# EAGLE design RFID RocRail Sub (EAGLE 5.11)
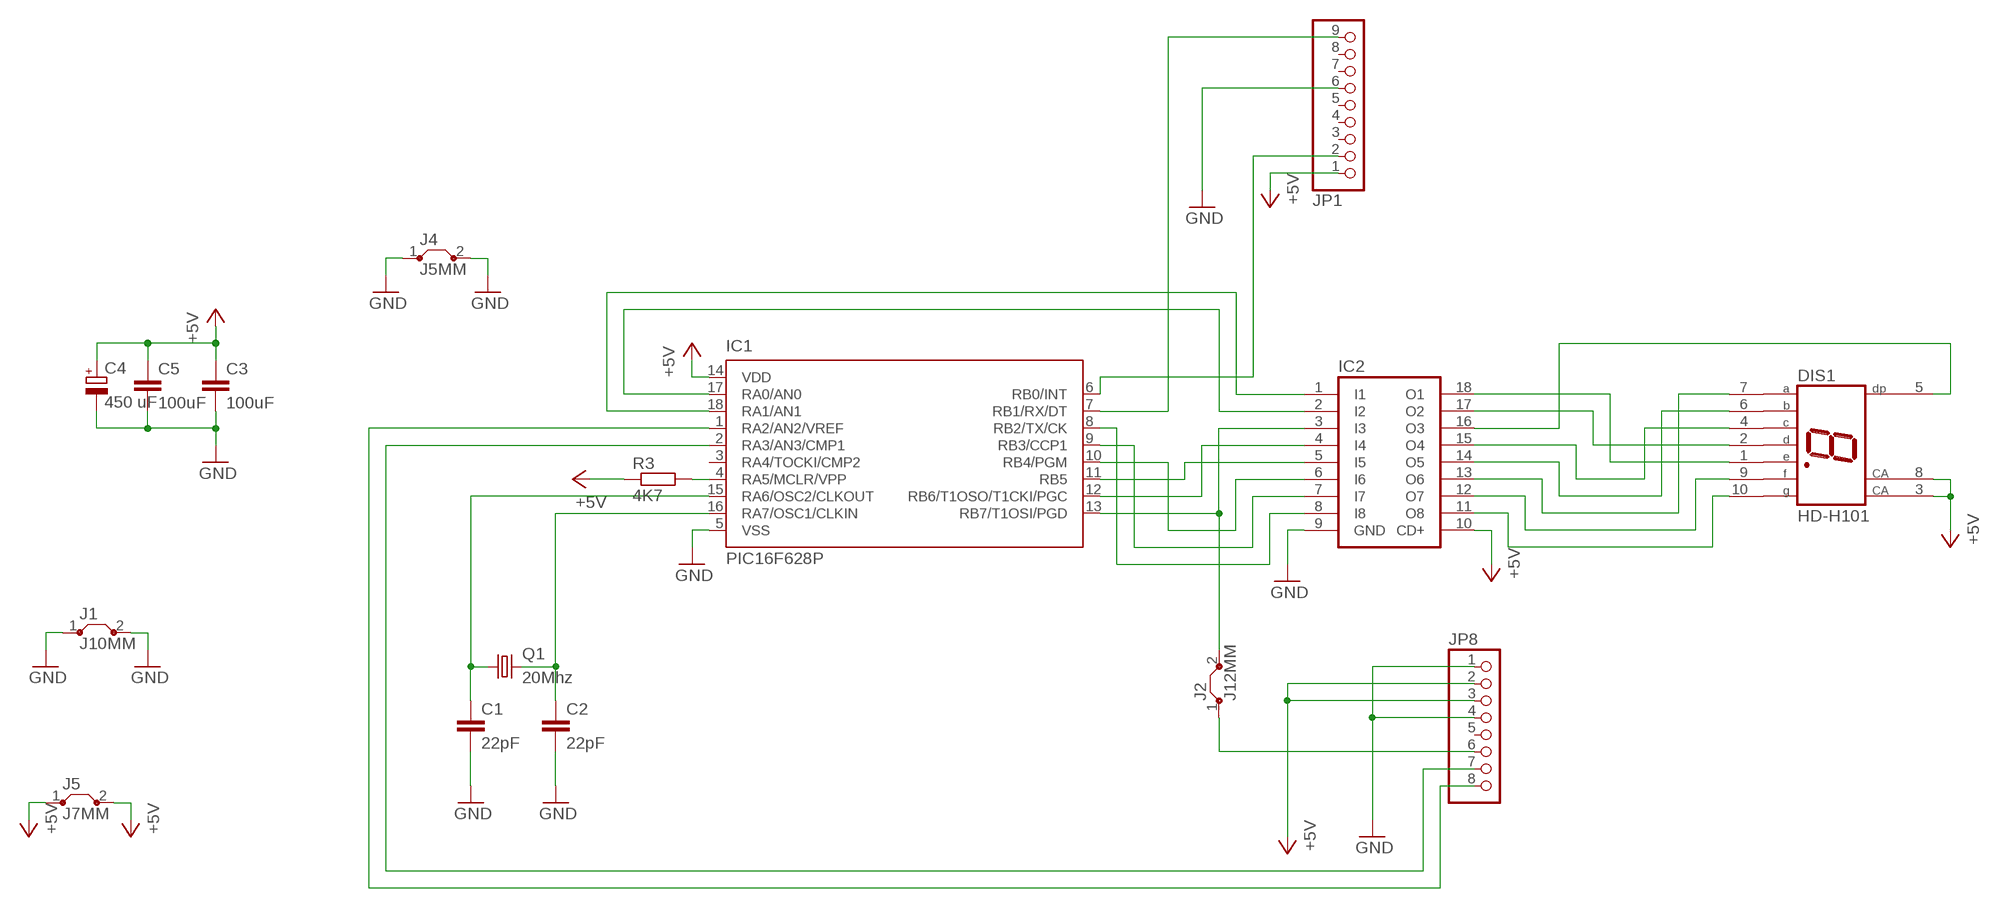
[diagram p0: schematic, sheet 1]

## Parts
C1  22pF  C-EU050-025X075  [C050-025X075]
C2  22pF  C-EU050-025X075  [C050-025X075]
C3  100uF  C-EU050-025X075  [C050-025X075]
C4  450 uF  CPOL-EUE5-13  [E5-13]
C5  100uF  C-EU050-025X075  [C050-025X075]
DIS1  HD-H101  [HDSP-M]
IC1  PIC16F628P  [DIL18]
IC2  ULN2803A  [DIL18]
J1  J10MM  [10]
J2  J12MM  [12]
J4  J5MM  [05]
J5  J7MM  [07]
JP1  PINHD-1X9  [1X09]
JP8  PINHD-1X8  [1X08]
Q1  20Mhz  CRYSTALHC18U-V  [HC18U-V]
R3  4K7  R-EU_0207/10  [0207/10]

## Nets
+5V: C3.1 C4.+ C5.1 DIS1.3(CA) DIS1.8(CA) IC1.14(VDD) IC2.10(CD+) J5.1 J5.2 JP1.1 JP8.2 JP8.3 R3.1
GND: C1.2 C2.2 C3.2 C4.- C5.2 IC1.5(VSS) IC2.9(GND) J1.1 J1.2 J4.1 J4.2 JP1.6 JP8.1 JP8.4
N$1: DIS1.1(E) IC2.18(O1)
N$2: DIS1.2(D) IC2.17(O2)
N$3: DIS1.5(DP) IC2.16(O3)
N$5: DIS1.6(B) IC2.14(O5)
N$6: DIS1.7(A) IC2.13(O6)
N$7: DIS1.9(F) IC2.12(O7)
N$8: DIS1.10(G) IC2.11(O8)
N$9: C1.1 IC1.15(RA6/OSC2/CLKOUT) Q1.1
N$10: IC1.18(RA1/AN1) IC2.1(I1)
N$11: IC1.17(RA0/AN0) IC2.2(I2)
N$12: IC1.13(RB7/T1OSI/PGD) IC2.3(I3) J2.2
N$13: J2.1 JP8.6
N$14: IC1.11(RB5) IC2.5(I5)
N$15: IC1.10(RB4/PGM) IC2.6(I6)
N$16: IC1.9(RB3/CCP1) IC2.7(I7)
N$17: IC1.8(RB2/TX/CK) IC2.8(I8)
N$18: IC1.12(RB6/T1OSO/T1CKI/PGC) IC2.4(I4)
N$19: IC1.1(RA2/AN2/VREF) JP8.8
N$20: IC1.2(RA3/AN3/CMP1) JP8.7
N$21: IC1.6(RB0/INT) JP1.2
N$22: IC1.7(RB1/RX/DT) JP1.9
N$23: DIS1.4(C) IC2.15(O4)
N$30: C2.1 IC1.16(RA7/OSC1/CLKIN) Q1.2
N$31: IC1.4(RA5/MCLR/VPP) R3.2
Unconnected: IC1.3(RA4/TOCKI/CMP2) JP1.3 JP1.4 JP1.5 JP1.7 JP1.8 JP8.5

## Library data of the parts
C1-C3 C5 = rcl:C-EU: CAPACITOR, European symbol
C4 = rcl:CPOL-EU: POLARIZED CAPACITOR, European symbol
DIS1 = display-hp:HD-H101: LED DISPLAY 1-character 7 segment, decimal point right; OC_FARNELL: unknown; OC_NEWARK: unknown
IC1 = microchip:PIC16F62*: FLASH-Based 8-Bit CMOS Microcontroller Source: http://ww1.microchip.com/downloads/en/DeviceDoc/40300C.pdf; MF: MICROCHIP; MPN: PIC16F628-04I/P; OC_FARNELL: 9760407; OC_NEWARK: 19C7272
IC2 = uln-udn:ULN2803A: DRIVER ARRAY
J1 J2 J4 J5 = jumper:J: Bridge
JP1 = pinhead:PINHD-1X9: PIN HEADER
JP8 = pinhead:PINHD-1X8: PIN HEADER
Q1 = crystal:CRYSTAL: CRYSTAL
R3 = rcl:R-EU_: RESISTOR, European symbol

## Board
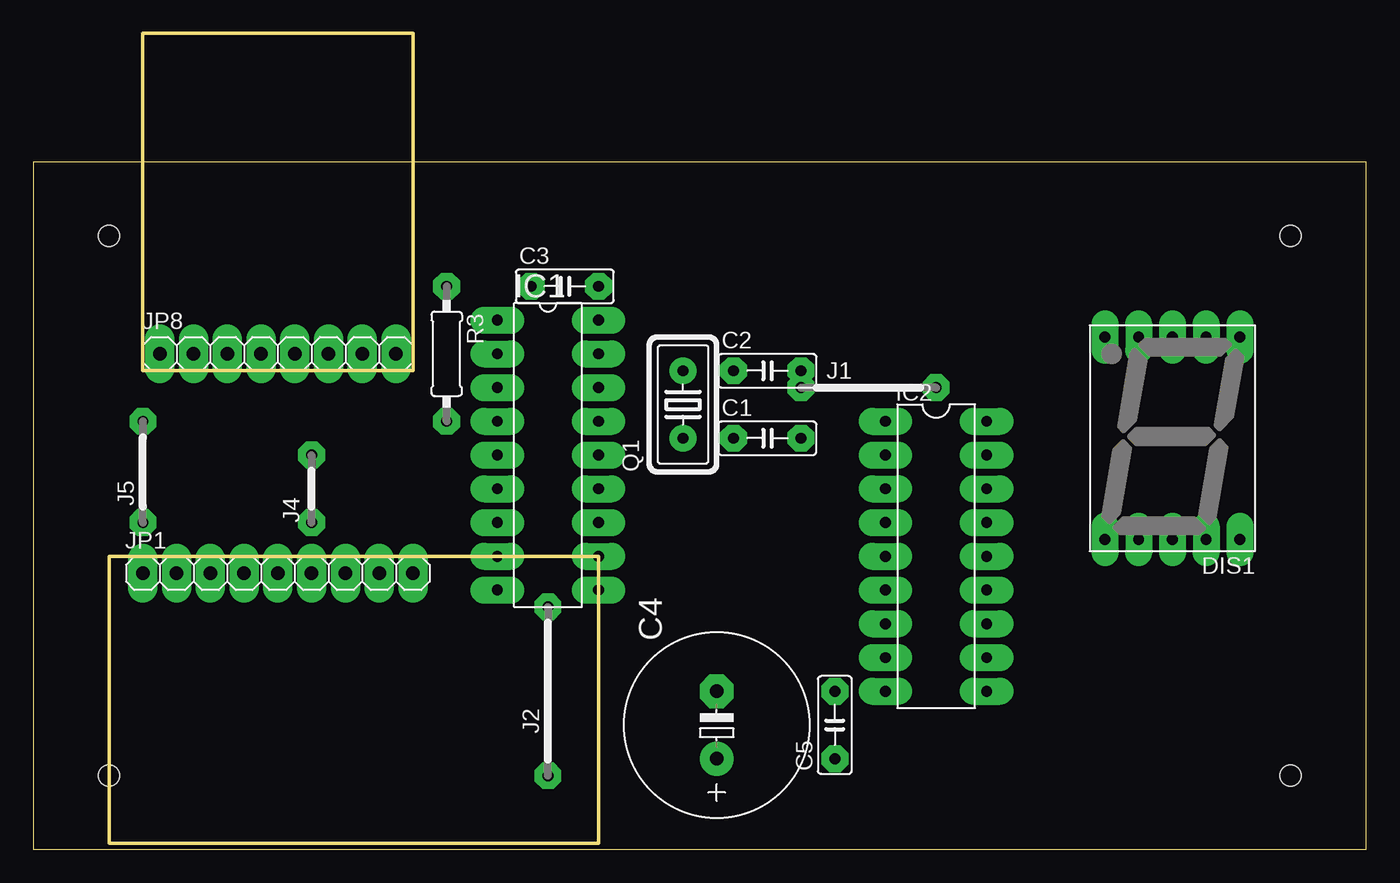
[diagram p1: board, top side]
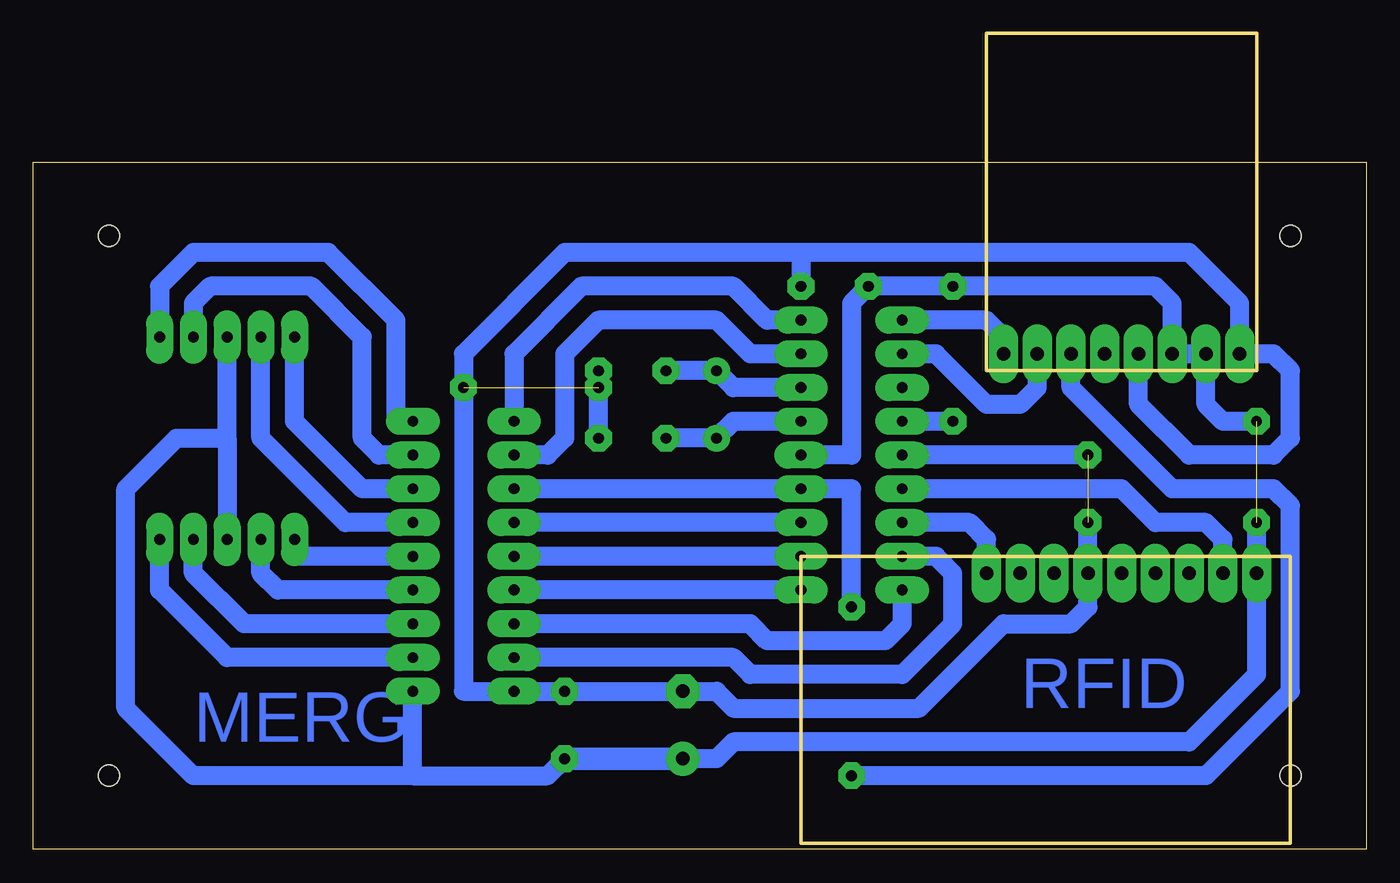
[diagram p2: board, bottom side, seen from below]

Size 100.31 x 61.43 mm. Coordinates in mm from the lower left corner, seen from the top.
Outline: 0,0 100.31,0 100.31,51.74 0,51.74 0,0
Outline: 8.25,36.03 8.25,61.43 28.57,61.43 28.57,36.03 8.25,36.03
Outline: 5.71,22.06 5.71,0.47 42.54,0.47 42.54,22.06 5.71,22.06
Copper layers (1*16): Top 1mm / dielectric 1.5mm / Bottom 1mm
Design rules "DRC settings middle": minimum track width 1.2mm, minimum drill 24mil, track to track 0.4mm, track to pad 0.4mm, pad to pad 0.4mm, via to via 0.4mm, smd to smd 8mil, copper to edge 0.5mm, drill to drill 0.5mm, minimum pad ring 0.6mm, minimum via ring 1mm, stop-mask expansion 4mil, vias tented up to drill 0mil, thermal gap 10mil
Holes 1.6 mm at 5.71,46.19 94.61,46.19 5.71,5.55 94.61,5.55

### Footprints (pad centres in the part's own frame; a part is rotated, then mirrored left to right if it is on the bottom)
C050-025X075 = drill 0.813 octagon: 1 -2.54,0; 2 2.54,0
E5-13 = drill 1.016 pad 2.54 round: + -2.54,0 | drill 1.016 pad 2.54 octagon: - 2.54,0
HDSP-M = drill 0.813 long: 1 -5.08,-7.62; 2 -2.54,-7.62; 3 0,-7.62; 4 2.54,-7.62; 5 5.08,-7.62; 6 5.08,7.62; 7 2.54,7.62; 8 0,7.62; 9 -2.54,7.62; 10 -5.08,7.62
DIL18 = drill 0.813 long: 1 -10.16,-3.81; 2 -7.62,-3.81; 3 -5.08,-3.81; 4 -2.54,-3.81; 5 0,-3.81; 6 2.54,-3.81; 7 5.08,-3.81; 8 7.62,-3.81; 9 10.16,-3.81; 10 10.16,3.81; 11 7.62,3.81; 12 5.08,3.81; 13 2.54,3.81; 14 0,3.81; 15 -2.54,3.81; 16 -5.08,3.81; 17 -7.62,3.81; 18 -10.16,3.81
10 = drill 0.813 pad 1.6 octagon: 1 -5.08,0; 2 5.08,0
12 = drill 0.813 pad 1.6 octagon: 1 -6.35,0; 2 6.35,0
05 = drill 0.813 pad 1.6 octagon: 1 -2.54,0; 2 2.54,0
07 = drill 0.813 pad 1.6 octagon: 1 -3.81,0; 2 3.81,0
1X09 = drill 1.016 long: 1 -10.16,0; 2 -7.62,0; 3 -5.08,0; 4 -2.54,0; 5 0,0; 6 2.54,0; 7 5.08,0; 8 7.62,0; 9 10.16,0
1X08 = drill 1.016 long: 1 -8.89,0; 2 -6.35,0; 3 -3.81,0; 4 -1.27,0; 5 1.27,0; 6 3.81,0; 7 6.35,0; 8 8.89,0
HC18U-V = drill 0.813 round: 1 -2.54,0; 2 2.54,0
0207/10 = drill 0.813 octagon: 1 -5.08,0; 2 5.08,0

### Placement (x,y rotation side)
C1  55.24,30.95 0 top
C2  55.24,36.03 0 top
C3  40,42.38 0 top
C4  51.43,9.36 90 top
C5  60.32,9.36 90 top
DIS1  85.72,30.95 180 top
IC1  38.73,29.68 270 top
IC2  67.94,22.06 270 top
J1  62.86,34.76 0 top
J2  38.73,11.9 90 top
J4  20.95,27.14 90 top
J5  8.25,28.41 90 top
JP1  18.41,20.79 0 top
JP8  18.41,37.3 0 top
Q1  48.89,33.49 90 top
R3  31.11,37.3 270 top

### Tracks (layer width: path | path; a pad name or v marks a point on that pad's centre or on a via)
+5V  (1 unrouted)
  Bottom 1.422: 85.72,30.95 DIS1.8 | 85.72,30.95 DIS1.3 | 71.75,5.55 88.26,5.55 93.34,10.63 93.34,27.14 89.53,30.95 85.72,30.95 | 71.75,5.55 IC2.10 | C4.+ 48.89,6.82 47.62,8.09 13.33,8.09 8.25,13.17 JP1.1 J5.1 | IC1.14 38.73,29.68 38.73,41.11 C3.1 R3.1 15.87,42.38 14.6,41.11 JP8.3 JP8.2 12.06,33.49 10.79,32.22 J5.2 | 71.75,5.55 61.59,5.55 C5.1
  Bottom 1.676: C4.+ C5.1
GND  (2 unrouted)
  Bottom 1.422: JP8.4 17.14,33.49 13.33,29.68 6.98,29.68 5.71,30.95 5.71,36.03 6.98,37.3 JP8.1 9.52,41.11 13.33,44.92 42.54,44.92 | C2.2 J1.1 C1.2 | J4.2 IC1.5 | J4.1 JP1.6 20.95,18.25 22.22,16.98 27.3,16.98 33.65,10.63 47.62,10.63 48.89,11.9 C4.- C5.2 IC2.9 67.94,11.9 J1.2 67.94,37.3 60.32,44.92 42.54,44.92 | 42.54,44.92 C3.2
N$1
  Bottom 1.422: IC2.18 73.02,32.22 73.02,39.84 78.1,44.92 88.26,44.92 90.8,42.38 DIS1.1
N$2
  Bottom 1.422: IC2.17 74.29,29.68 75.56,30.95 75.56,38.57 79.37,42.38 86.99,42.38 88.26,41.11 DIS1.2
N$3
  Bottom 1.422: IC2.16 75.56,27.14 80.64,32.22 DIS1.5
N$5
  Bottom 1.422: IC2.14 80.64,22.06 DIS1.6
N$6
  Bottom 1.422: IC2.13 81.91,19.52 83.18,20.79 DIS1.7
N$7
  Bottom 1.422: IC2.12 84.45,16.98 88.26,20.79 DIS1.9
N$8
  Bottom 1.422: IC2.11 85.72,14.44 90.8,19.52 DIS1.10
N$9
  Bottom 1.422: IC1.15 47.62,32.22 Q1.1 C1.1
N$10
  Bottom 1.422: IC1.18 45.08,39.84 47.62,42.38 59.05,42.38 64.13,37.3 IC2.1
N$11
  Bottom 1.422: IC1.17 46.35,37.3 48.89,39.84 57.78,39.84 60.32,37.3 60.32,30.95 61.59,29.68 IC2.2
N$12
  Bottom 1.422: IC2.3 IC1.13 38.73,27.14 J2.2
N$13
  Bottom 1.422: J2.1 12.06,5.55 5.71,11.9 5.71,25.87 6.98,27.14 14.6,27.14 22.22,34.76 JP8.6
N$14
  Bottom 1.422: IC1.11 IC2.5
N$15
  Bottom 1.422: IC1.10 IC2.6
N$16
  Bottom 1.422: IC2.7 46.35,16.98 45.08,15.71 36.19,15.71 34.92,16.98 IC1.9
N$17
  Bottom 1.422: IC2.8 47.62,14.44 46.35,13.17 34.92,13.17 31.11,16.98 31.11,20.79 32.38,22.06 IC1.8
N$18
  Bottom 1.422: IC1.12 IC2.4
N$19
  Bottom 1.422: IC1.1 28.57,39.84 27.3,38.57 JP8.8
N$20
  Bottom 1.422: IC1.2 32.38,37.3 28.57,33.49 26.03,33.49 24.76,34.76 JP8.7
N$21
  Bottom 1.422: JP1.2 10.79,23.33 12.06,24.6 15.87,24.6 18.41,27.14 IC1.6
N$22
  Bottom 1.422: IC1.7 29.84,24.6 28.57,23.33 JP1.9
N$23
  Bottom 1.422: IC2.15 76.83,24.6 83.18,30.95 DIS1.4
N$30
  Bottom 1.422: IC1.16 47.62,34.76 Q1.2 C2.1
N$31
  Bottom 1.422: R3.2 IC1.4

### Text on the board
Bottom: RFID | MERG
